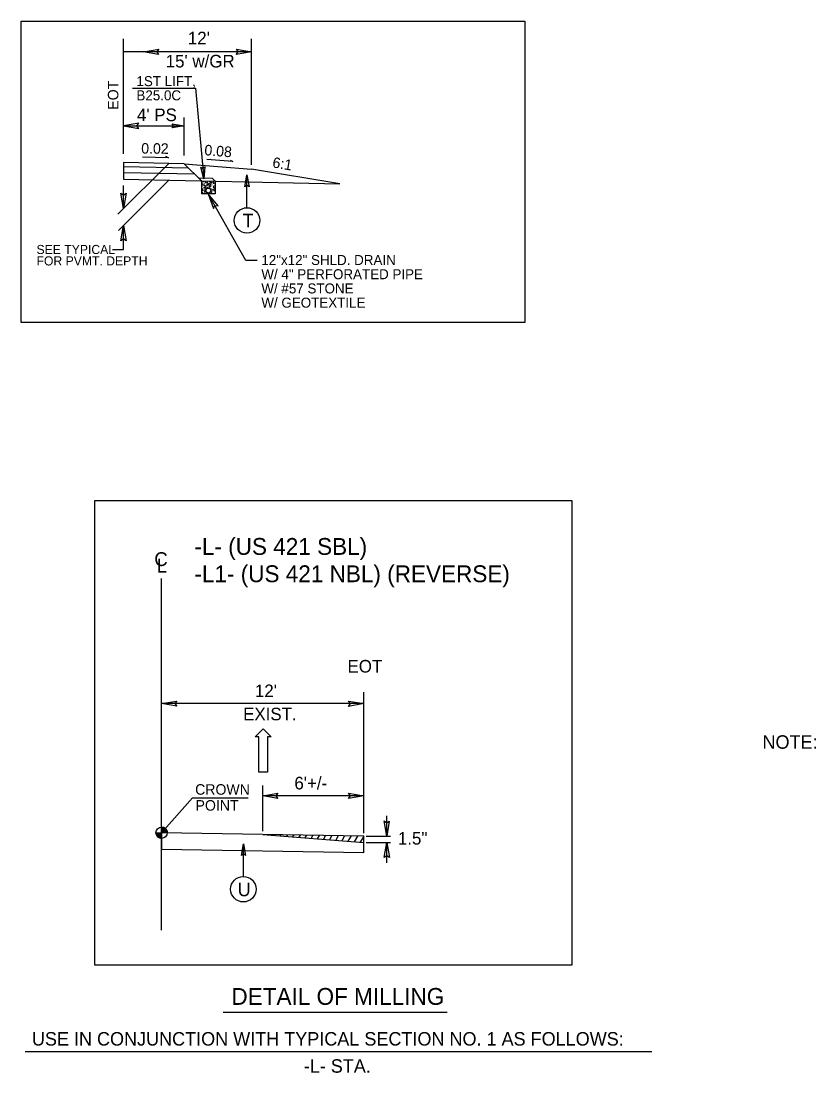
# Model space of a CAD drawing. Extents: x 573813 to 575363, y -54752 to -53123.
# Drawn here: x 574448.5 to 574555.8, y -53316.8 to -53174.7 of the extents above; entities that cross this region are included whole.
import ezdxf

# ---------------------------------------------------------------- set-up
doc = ezdxf.new("R2010")
doc.units = 0
for name, color, linetype in [('Old_Level_1', 7, 'Continuous'), ('Old_Level_11', 7, 'Continuous'), ('Old_Level_2', 7, 'Continuous'), ('Old_Level_3', 7, 'Continuous'), ('Old_Level_4', 7, 'Continuous'), ('Prop Pavement Schedule Description CELL', 7, 'Continuous'), ('Typical Curb CELL', 7, 'Continuous'), ('Typical Detail Wedge2 CELL', 7, 'Continuous'), ('Typical Grade Point Symbol CELL', 7, 'Continuous'), ('Typical ID Circle CELL', 7, 'Continuous'), ('Typical Terminator CELL', 7, 'Continuous'), ('Typical Text ID Circle CELL', 7, 'Continuous')]:
    doc.layers.add(name, color=color, linetype=linetype)

msp = doc.modelspace()

# ---------------------------------------------------------------- linework, layer by layer
at = {"layer": 'Old_Level_1'}
for p, q in [((574470.54, -53194), (574462.37, -53193.83)), ((574468.42, -53193.19), (574464.91, -53193.12)), ((574468.04, -53193), (574468.42, -53193.19)), ((574470.54, -53194), (574472.86, -53196.32)), ((574470.54, -53194), (574479.64, -53194.72)), ((574477.11, -53193.72), (574473.61, -53193.42)), ((574476.74, -53193.51), (574477.11, -53193.72)), ((574471.14, -53194.6), (574462.37, -53194.42)), ((574462.37, -53195.18), (574471.93, -53195.38)), ((574491.56, -53196.71), (574479.64, -53194.72)), ((574462.37, -53196.1), (574491.56, -53196.71)), ((574472.44, -53195.89), (574474.31, -53195.93)), ((574474.31, -53195.93), (574474.74, -53196.36)), ((574494.78, -53284.83), (574467.5, -53284.36)), ((574467.5, -53284.36), (574467.5, -53286.63)), ((574494.78, -53287.1), (574494.78, -53284.83)), ((574494.78, -53287.1), (574467.5, -53286.63))]:
    msp.add_line(p, q, dxfattribs=at)
at = {"layer": 'Old_Level_11'}
for p, q in [((574462.37, -53192.66), (574462.37, -53177.15)), ((574479.64, -53194.15), (574479.64, -53177.15)), ((574479.64, -53178.88), (574462.37, -53178.88)), ((574463.58, -53183.8), (574472.05, -53183.8)), ((574472.05, -53183.8), (574473.21, -53196.06)), ((574470.54, -53192.87), (574470.54, -53187.76)), ((574462.37, -53188.88), (574470.54, -53188.88)), ((574468.47, -53193.95), (574461.6, -53200.82)), ((574468.47, -53196.23), (574461.66, -53203.03)), ((574462.37, -53200.03), (574462.37, -53196.95)), ((574478.88, -53207.09), (574473.8, -53198.07)), ((574462.33, -53205.57), (574462.33, -53202.36)), ((574460.86, -53205.57), (574462.33, -53205.57)), ((574480.39, -53207.09), (574478.88, -53207.09)), ((574494.78, -53282.15), (574494.78, -53265.39)), ((574494.78, -53266.93), (574467.5, -53266.93)), ((574494.78, -53284.42), (574494.78, -53274.2)), ((574494.78, -53284.37), (574494.78, -53274.31)), ((574481.14, -53284.15), (574481.14, -53277.98)), ((574494.78, -53279.37), (574481.14, -53279.37)), ((574467.5, -53284.36), (574471.66, -53279.63)), ((574471.66, -53279.63), (574479.16, -53279.63)), ((574497.88, -53284.83), (574497.88, -53282.06)), ((574495.09, -53284.83), (574498.38, -53284.83)), ((574495.09, -53285.67), (574498.38, -53285.67)), ((574497.88, -53288.44), (574497.88, -53285.67)), ((574475.82, -53308.62), (574506.04, -53308.62)), ((574449.09, -53313.91), (574533.67, -53313.91))]:
    msp.add_line(p, q, dxfattribs=at)
for points in [[(574467.09, -53179.23), (574465.05, -53178.88), (574467.1, -53178.51), (574466.84, -53178.88)], [(574477.59, -53178.53), (574479.64, -53178.88), (574477.58, -53179.24), (574477.84, -53178.88)], [(574464.41, -53188.53), (574462.37, -53188.88), (574464.43, -53189.25), (574464.16, -53188.88)], [(574468.9, -53188.6), (574470.54, -53188.88), (574468.9, -53189.17), (574469.1, -53188.88)], [(574473.34, -53194.4), (574473.21, -53196.06), (574472.77, -53194.45), (574473.08, -53194.63)], [(574462.72, -53197.98), (574462.37, -53200.03), (574462, -53197.97), (574462.37, -53198.23)], [(574475.11, -53199.68), (574473.8, -53198.07), (574474.49, -53200.04), (574474.68, -53199.64)], [(574461.98, -53204.41), (574462.33, -53202.36), (574462.69, -53204.42), (574462.33, -53204.16)], [(574469.54, -53267.29), (574467.5, -53266.93), (574469.55, -53266.57), (574469.29, -53266.93)], [(574492.74, -53266.58), (574494.78, -53266.93), (574492.73, -53267.3), (574492.99, -53266.93)], [(574483.18, -53279.73), (574481.14, -53279.37), (574483.2, -53279.01), (574482.93, -53279.37)], [(574492.74, -53279.02), (574494.78, -53279.37), (574492.72, -53279.74), (574492.99, -53279.37)], [(574498.23, -53282.78), (574497.88, -53284.83), (574497.52, -53282.77), (574497.88, -53283.03)], [(574497.53, -53287.72), (574497.88, -53285.67), (574498.25, -53287.73), (574497.88, -53287.47)]]:
    msp.add_lwpolyline(points, close=True, dxfattribs=at)
at = {"layer": 'Old_Level_2'}
for p, q in [((574462.37, -53193.83), (574462.37, -53196.1)), ((574472.86, -53196.32), (574472.86, -53198.07)), ((574474.74, -53196.36), (574474.74, -53198.07)), ((574474.74, -53198.07), (574472.86, -53198.07)), ((574467.5, -53267.19), (574467.5, -53250.04)), ((574467.5, -53297.53), (574467.5, -53267.19))]:
    msp.add_line(p, q, dxfattribs=at)
msp.add_circle((574473.8, -53197.62), 0.337, dxfattribs=at)
at = {"layer": 'Old_Level_4'}
for p, q in [((574480.13, -53271.43), (574481.19, -53270.35)), ((574481.19, -53270.35), (574482.28, -53271.43)), ((574480.64, -53271.43), (574480.13, -53271.43)), ((574480.64, -53276.2), (574480.64, -53271.43)), ((574482.28, -53271.43), (574481.77, -53271.43)), ((574481.77, -53271.43), (574481.77, -53276.2)), ((574481.77, -53276.2), (574480.64, -53276.2))]:
    msp.add_line(p, q, dxfattribs=at)
at = {"layer": 'Prop Pavement Schedule Description CELL'}
for points in [[(574448.52, -53174.73), (574516.53, -53174.73), (574516.53, -53215.45), (574448.52, -53215.45)], [(574458.47, -53239.49), (574522.88, -53239.49), (574522.88, -53302.23), (574458.47, -53302.23)]]:
    msp.add_lwpolyline(points, close=True, dxfattribs=at)
at = {"layer": 'Typical Curb CELL'}
for p, q in [((574473.09, -53196.77), (574473.01, -53196.78)), ((574473.01, -53196.78), (574473.05, -53196.9)), ((574473.05, -53196.9), (574473.09, -53196.77)), ((574473.31, -53197.03), (574473.35, -53197.19)), ((574473.39, -53197.09), (574473.31, -53197.03)), ((574473.37, -53196.42), (574473.42, -53196.59)), ((574473.46, -53196.49), (574473.37, -53196.42)), ((574473.42, -53196.59), (574473.46, -53196.49)), ((574473.85, -53196.78), (574473.77, -53196.79)), ((574473.77, -53196.79), (574473.81, -53196.91)), ((574473.81, -53196.91), (574473.85, -53196.78)), ((574473.9, -53196.97), (574473.94, -53197.13)), ((574473.98, -53197.03), (574473.9, -53196.97)), ((574473.94, -53197.13), (574473.98, -53197.03)), ((574474.16, -53196.8), (574474.09, -53196.81)), ((574474.09, -53196.81), (574474.12, -53196.93)), ((574474.12, -53196.44), (574474.17, -53196.6)), ((574474.21, -53196.5), (574474.12, -53196.44)), ((574474.12, -53196.93), (574474.16, -53196.8)), ((574474.17, -53196.6), (574474.21, -53196.5)), ((574474.44, -53196.45), (574474.49, -53196.62)), ((574474.53, -53196.52), (574474.44, -53196.45)), ((574474.48, -53197.04), (574474.52, -53197.2)), ((574474.57, -53197.11), (574474.48, -53197.04)), ((574474.49, -53196.62), (574474.53, -53196.52)), ((574473.03, -53197.37), (574472.95, -53197.38)), ((574472.95, -53197.38), (574472.99, -53197.5)), ((574473.04, -53197.87), (574472.96, -53197.89)), ((574472.96, -53197.89), (574473, -53198.01)), ((574472.99, -53197.5), (574473.03, -53197.37)), ((574473, -53198.01), (574473.04, -53197.87)), ((574473.32, -53197.53), (574473.37, -53197.69)), ((574473.41, -53197.6), (574473.32, -53197.53)), ((574473.35, -53197.19), (574473.39, -53197.09)), ((574473.37, -53197.69), (574473.41, -53197.6)), ((574474.2, -53197.38), (574474.12, -53197.4)), ((574474.12, -53197.4), (574474.16, -53197.52)), ((574474.22, -53197.84), (574474.14, -53197.86)), ((574474.14, -53197.86), (574474.18, -53197.97)), ((574474.16, -53197.52), (574474.2, -53197.38)), ((574474.18, -53197.97), (574474.22, -53197.84)), ((574474.5, -53197.5), (574474.54, -53197.66)), ((574474.58, -53197.56), (574474.5, -53197.5)), ((574474.52, -53197.2), (574474.57, -53197.11)), ((574474.54, -53197.66), (574474.58, -53197.56))]:
    msp.add_line(p, q, dxfattribs=at)
for centre in [(574472.88, -53197.04), (574472.92, -53196.77), (574472.92, -53196.94), (574472.94, -53196.69), (574472.94, -53196.44), (574472.96, -53196.47), (574473.09, -53196.47), (574473.13, -53196.87), (574473.15, -53196.64), (574473.25, -53196.49), (574473.28, -53196.92), (574473.3, -53196.63), (574473.31, -53196.73), (574473.32, -53196.97), (574473.38, -53196.37), (574473.46, -53196.66), (574473.47, -53196.98), (574473.49, -53197.01), (574473.56, -53196.51), (574473.57, -53196.94), (574473.58, -53196.81), (574473.62, -53196.66), (574473.61, -53197.02), (574473.67, -53196.78), (574473.67, -53196.95), (574473.69, -53196.7), (574473.7, -53196.45), (574473.71, -53196.48), (574473.77, -53197.03), (574473.84, -53196.48), (574473.88, -53196.88), (574473.9, -53196.65), (574473.91, -53196.91), (574473.99, -53196.8), (574473.99, -53196.97), (574474, -53196.5), (574474.01, -53196.72), (574474.01, -53196.47), (574474.03, -53196.5), (574474.04, -53196.93), (574474.05, -53196.64), (574474.05, -53197.05), (574474.07, -53196.74), (574474.09, -53197.05), (574474.13, -53196.38), (574474.16, -53196.5), (574474.2, -53196.9), (574474.21, -53196.67), (574474.22, -53196.67), (574474.32, -53196.52), (574474.32, -53196.52), (574474.32, -53196.95), (574474.33, -53196.82), (574474.35, -53196.95), (574474.37, -53196.66), (574474.37, -53196.67), (574474.38, -53196.76), (574474.45, -53196.4), (574474.49, -53196.98), (574474.53, -53196.69), (574474.63, -53196.54), (574474.64, -53196.97), (574474.65, -53196.84), (574474.69, -53196.69), (574472.89, -53197.8), (574472.9, -53197.07), (574472.89, -53197.54), (574472.91, -53197.58), (574473.02, -53197.07), (574473.04, -53197.58), (574473.06, -53197.48), (574473.08, -53197.98), (574473.09, -53197.25), (574473.1, -53197.75), (574473.18, -53197.09), (574473.2, -53197.6), (574473.22, -53197.52), (574473.23, -53197.23), (574473.23, -53198.03), (574473.25, -53197.33), (574473.25, -53197.74), (574473.26, -53197.84), (574473.33, -53197.47), (574473.39, -53197.27), (574473.41, -53197.77), (574473.44, -53197.32), (574473.44, -53197.48), (574473.46, -53197.23), (574473.5, -53197.11), (574473.52, -53197.41), (574473.52, -53198.04), (574473.53, -53197.88), (574473.53, -53198.05), (574473.53, -53197.91), (574473.55, -53197.26), (574473.68, -53197.19), (574473.74, -53197.98), (574473.82, -53197.17), (574473.84, -53197.28), (574473.89, -53198.03), (574473.98, -53197.21), (574474.04, -53197.31), (574474.04, -53198.02), (574474.07, -53197.09), (574474.11, -53197.35), (574474.14, -53197.2), (574474.17, -53197.61), (574474.18, -53198.04), (574474.19, -53197.91), (574474.2, -53197.09), (574474.21, -53197.55), (574474.22, -53197.77), (574474.24, -53197.49), (574474.25, -53197.95), (574474.26, -53197.26), (574474.28, -53197.72), (574474.36, -53197.11), (574474.37, -53197.56), (574474.39, -53197.54), (574474.41, -53197.25), (574474.41, -53197.99), (574474.42, -53197.35), (574474.42, -53197.71), (574474.44, -53197.81), (574474.51, -53197.44), (574474.57, -53197.28), (574474.58, -53197.74), (574474.67, -53197.12), (574474.68, -53197.55), (574474.69, -53197.42), (574474.69, -53197.58), (574474.69, -53198.01), (574474.71, -53197.88), (574474.72, -53197.28)]:
    msp.add_circle(centre, 0.00687, dxfattribs=at)
at = {"layer": 'Typical Detail Wedge2 CELL'}
for p, q in [((574481.14, -53284.59), (574494.78, -53285.67)), ((574481.89, -53284.6), (574481.86, -53284.65)), ((574482.75, -53284.62), (574482.69, -53284.71)), ((574483.61, -53284.63), (574483.52, -53284.78)), ((574484.47, -53284.65), (574484.35, -53284.85)), ((574485.33, -53284.66), (574485.18, -53284.91)), ((574486.19, -53284.68), (574486.01, -53284.98)), ((574487.05, -53284.69), (574486.84, -53285.04)), ((574487.91, -53284.71), (574487.67, -53285.11)), ((574488.77, -53284.72), (574488.5, -53285.17)), ((574489.62, -53284.74), (574489.33, -53285.24)), ((574490.48, -53284.75), (574490.16, -53285.31)), ((574491.34, -53284.77), (574490.99, -53285.37)), ((574492.2, -53284.78), (574491.82, -53285.44)), ((574493.06, -53284.8), (574492.65, -53285.5)), ((574493.92, -53284.81), (574493.48, -53285.57)), ((574494.78, -53284.83), (574494.31, -53285.64))]:
    msp.add_line(p, q, dxfattribs=at)
at = {"layer": 'Typical Grade Point Symbol CELL'}
for p, q in [((574467.5, -53284.36), (574467.5, -53283.59)), ((574466.73, -53284.36), (574467.5, -53284.36)), ((574467.49, -53285.12), (574467.5, -53284.36)), ((574467.5, -53284.36), (574467.49, -53285.12)), ((574468.26, -53284.36), (574467.5, -53284.36))]:
    msp.add_line(p, q, dxfattribs=at)
for points in [[(574467.5, -53283.59), (574467.5, -53283.59), (574467.5, -53284.36)], [(574467.52, -53283.59), (574467.52, -53284.36)], [(574467.53, -53283.6), (574467.53, -53284.36)], [(574467.55, -53283.6), (574467.55, -53284.36)], [(574467.56, -53283.6), (574467.56, -53284.36)], [(574467.58, -53283.6), (574467.58, -53284.36)], [(574467.59, -53283.6), (574467.59, -53284.36)], [(574467.61, -53283.6), (574467.61, -53284.36)], [(574467.62, -53283.6), (574467.62, -53284.36)], [(574467.64, -53283.61), (574467.64, -53284.36)], [(574467.65, -53283.61), (574467.65, -53284.36)], [(574467.67, -53283.61), (574467.67, -53284.36)], [(574467.69, -53283.62), (574467.69, -53284.36)], [(574467.7, -53283.62), (574467.7, -53284.36)], [(574467.72, -53283.63), (574467.72, -53284.36)], [(574467.73, -53283.63), (574467.73, -53284.36)], [(574467.75, -53283.64), (574467.75, -53284.36)], [(574467.76, -53283.64), (574467.76, -53284.36)], [(574467.78, -53283.65), (574467.78, -53284.36)], [(574467.79, -53283.65), (574467.79, -53284.36)], [(574467.81, -53283.66), (574467.81, -53284.36)], [(574467.82, -53283.67), (574467.82, -53284.36)], [(574467.84, -53283.67), (574467.84, -53284.36)], [(574467.85, -53283.68), (574467.85, -53284.36)], [(574467.87, -53283.69), (574467.87, -53284.36)], [(574467.88, -53283.7), (574467.88, -53284.36)], [(574467.9, -53283.71), (574467.9, -53284.36)], [(574466.74, -53284.36), (574466.74, -53284.44)], [(574466.75, -53284.36), (574466.75, -53284.53)], [(574466.77, -53284.36), (574466.77, -53284.58)], [(574466.78, -53284.36), (574466.78, -53284.63)], [(574466.8, -53284.36), (574466.8, -53284.67)], [(574466.81, -53284.36), (574466.81, -53284.7)], [(574466.83, -53284.36), (574466.83, -53284.73)], [(574466.84, -53284.36), (574466.84, -53284.75)], [(574466.86, -53284.36), (574466.86, -53284.78)], [(574466.87, -53284.36), (574466.87, -53284.8)], [(574466.89, -53284.36), (574466.89, -53284.82)], [(574466.9, -53284.36), (574466.9, -53284.84)], [(574466.92, -53284.36), (574466.92, -53284.86)], [(574466.93, -53284.36), (574466.93, -53284.87)], [(574466.95, -53284.36), (574466.95, -53284.89)], [(574466.96, -53284.36), (574466.96, -53284.91)], [(574466.98, -53284.36), (574466.98, -53284.92)], [(574466.99, -53284.36), (574466.99, -53284.93)], [(574467.01, -53284.36), (574467.01, -53284.95)], [(574467.03, -53284.36), (574467.03, -53284.96)], [(574467.04, -53284.36), (574467.04, -53284.97)], [(574467.06, -53284.36), (574467.06, -53284.98)], [(574467.07, -53284.36), (574467.07, -53284.99)], [(574467.09, -53284.36), (574467.09, -53285)], [(574467.1, -53284.36), (574467.1, -53285.01)], [(574467.12, -53284.36), (574467.12, -53285.02)], [(574467.13, -53284.36), (574467.13, -53285.03)], [(574467.15, -53284.36), (574467.15, -53285.04)], [(574467.16, -53284.36), (574467.16, -53285.04)], [(574467.18, -53284.36), (574467.18, -53285.05)], [(574467.19, -53284.36), (574467.19, -53285.06)], [(574467.21, -53284.36), (574467.21, -53285.06)], [(574467.22, -53284.36), (574467.22, -53285.07)], [(574467.24, -53284.36), (574467.24, -53285.08)], [(574467.25, -53284.36), (574467.25, -53285.08)], [(574467.27, -53284.36), (574467.27, -53285.09)], [(574467.29, -53284.36), (574467.29, -53285.09)], [(574467.3, -53284.36), (574467.3, -53285.09)], [(574467.32, -53284.36), (574467.32, -53285.1)], [(574467.33, -53284.36), (574467.33, -53285.1)], [(574467.35, -53284.36), (574467.35, -53285.11)], [(574467.36, -53284.36), (574467.36, -53285.11)], [(574467.38, -53284.36), (574467.38, -53285.11)], [(574467.39, -53284.36), (574467.39, -53285.11)], [(574467.41, -53284.36), (574467.41, -53285.12)], [(574467.42, -53284.36), (574467.42, -53285.12)], [(574467.44, -53284.36), (574467.44, -53285.12)], [(574467.45, -53284.36), (574467.45, -53285.12)], [(574467.47, -53284.36), (574467.47, -53285.12)], [(574467.48, -53284.36), (574467.48, -53285.12), (574467.48, -53285.12)], [(574467.91, -53283.72), (574467.91, -53284.36)], [(574467.93, -53283.73), (574467.93, -53284.36)], [(574467.94, -53283.74), (574467.94, -53284.36)], [(574467.96, -53283.75), (574467.96, -53284.36)], [(574467.98, -53283.76), (574467.98, -53284.36)], [(574467.99, -53283.78), (574467.99, -53284.36)], [(574468.01, -53283.79), (574468.01, -53284.36)], [(574468.02, -53283.8), (574468.02, -53284.36)], [(574468.04, -53283.82), (574468.04, -53284.36)], [(574468.05, -53283.83), (574468.05, -53284.36)], [(574468.07, -53283.85), (574468.07, -53284.36)], [(574468.08, -53283.87), (574468.08, -53284.36)], [(574468.1, -53283.89), (574468.1, -53284.36)], [(574468.11, -53283.91), (574468.11, -53284.36)], [(574468.13, -53283.93), (574468.13, -53284.36)], [(574468.14, -53283.95), (574468.14, -53284.36)], [(574468.16, -53283.98), (574468.16, -53284.36)], [(574468.17, -53284.01), (574468.17, -53284.36)], [(574468.19, -53284.04), (574468.19, -53284.36)], [(574468.2, -53284.08), (574468.2, -53284.36)], [(574468.22, -53284.12), (574468.22, -53284.36)], [(574468.23, -53284.17), (574468.23, -53284.36)], [(574468.25, -53284.25), (574468.25, -53284.36)]]:
    msp.add_lwpolyline(points, dxfattribs=at)
msp.add_circle((574467.49, -53284.36), 0.763, dxfattribs=at)
for start, end in [(359.9905, 89.9905), (179.9905, 269.9905)]:
    msp.add_arc((574467.49, -53284.36), 0.763, start, end, dxfattribs=at)
at = {"layer": 'Typical ID Circle CELL'}
for p, q in [((574479.02, -53199.95), (574479.02, -53195.51)), ((574478.53, -53290.27), (574478.53, -53285.84))]:
    msp.add_line(p, q, dxfattribs=at)
for centre in [(574479.02, -53201.66), (574478.53, -53291.99)]:
    msp.add_circle(centre, 1.72, dxfattribs=at)
at = {"layer": 'Typical Terminator CELL'}
for points in [[(574478.75, -53197.1), (574479.02, -53195.51), (574479.3, -53197.11), (574479.02, -53196.9)], [(574478.26, -53287.43), (574478.53, -53285.84), (574478.82, -53287.43), (574478.53, -53287.23)]]:
    msp.add_lwpolyline(points, close=True, dxfattribs=at)

# ---------------------------------------------------------------- texts
at = {"layer": 'Old_Level_1'}
for s, height, rotation, p in [('EOT', 1.421, 89.9994, (574461.66, -53186.7)), ('0.02', 1.421, 359.3937, (574464.74, -53192.63)), ('0.08', 1.421, 355.3327, (574473.23, -53192.84)), ('6:1', 1.421, 350.5376, (574482.38, -53194.49)), ('EOT', 1.705, 0.0002, (574492.59, -53262.73)), ("12'", 1.705, 0.0002, (574480.09, -53266.05)), ('EXIST.', 1.705, 0.0002, (574478.5, -53269.18)), ('NOTE:', 1.819, 360, (574548.6, -53273.02)), ("6'+/-", 1.705, 0.0002, (574485.42, -53278.51)), ('1.5"', 1.705, 0.0002, (574499.39, -53285.97)), ('DETAIL OF MILLING', 2.2739, 360, (574476.92, -53307.61)), ('USE IN CONJUNCTION WITH TYPICAL SECTION NO. 1 AS FOLLOWS:', 1.8192, 360, (574449.99, -53313.11)), ('-L- STA. ', 1.819, 0, (574486.68, -53316.78))]:
    msp.add_text(s, height=height, rotation=rotation, dxfattribs=at).set_placement(p)
at = {"layer": 'Old_Level_11'}
for s, height, rotation, p in [("12'", 1.705, 0.0002, (574471.04, -53177.88)), ("15' w/GR", 1.705, 0.0002, (574468.05, -53181)), ('1ST LIFT,', 1.35, 360, (574464.1, -53183.52)), ('B25.0C', 1.35, 360, (574464.1, -53185.44)), ("4' PS", 1.705, 0.0018, (574464.17, -53188.25)), ('12"x12" SHLD. DRAIN', 1.3502, 360, (574480.96, -53207.68)), ('W/ 4" PERFORATED PIPE', 1.3502, 360, (574480.96, -53209.6)), ('W/ #57 STONE', 1.3502, 360, (574480.96, -53211.52)), ('W/ GEOTEXTILE', 1.3502, 360, (574480.96, -53213.44))]:
    msp.add_text(s, height=height, rotation=rotation, dxfattribs=at).set_placement(p)
at = {"layer": 'Old_Level_2'}
for s, rotation, p in [('C', 359.9999, (574466.51, -53248.34)), ('L', 359.9468, (574466.84, -53249.22))]:
    msp.add_text(s, height=1.87, rotation=rotation, dxfattribs=at).set_placement(p)
at = {"layer": 'Old_Level_3'}
for s, height, p in [('-L- (US 421 SBL)', 2.2739, (574471.92, -53246.83)), ('-L1- (US 421 NBL) (REVERSE)', 2.2739, (574471.92, -53250.52)), ('CROWN', 1.421, (574472.02, -53279.23)), ('POINT', 1.421, (574472.08, -53281.38))]:
    msp.add_text(s, height=height, rotation=359.9982, dxfattribs=at).set_placement(p)
at = {"layer": 'Prop Pavement Schedule Description CELL'}
msp.add_text('T', height=1.82, rotation=360, dxfattribs=at).set_placement((574478.42, -53202.57))
msp.add_text('U ', height=1.819, dxfattribs=at).set_placement((574477.76, -53292.94))
at = {"layer": 'Typical Text ID Circle CELL'}
for s, p in [('SEE TYPICAL', (574450.61, -53206.2)), ('FOR PVMT. DEPTH', (574450.61, -53207.74))]:
    msp.add_text(s, height=1.2298, dxfattribs=at).set_placement(p)

doc.saveas('drawing.dxf')
